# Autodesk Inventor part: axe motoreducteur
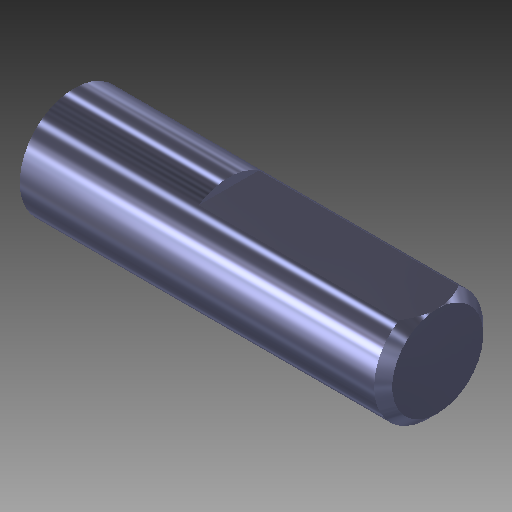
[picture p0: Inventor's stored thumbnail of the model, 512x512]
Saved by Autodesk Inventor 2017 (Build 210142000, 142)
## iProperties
Part Number: axe motoreducteur
Material: Générique
Document SubType Name: Modeling
Designer: ficho
Density: 1 g/cm^3
Appearance: Chrome - Bleu poli
Mass: 0.550661 g
Surface Area: 4.2614 cm^2
Volume: 0.550661 cm^3
Author: ficho
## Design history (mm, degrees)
sketch "Esquisse1"
  geometry: L1 (0, 0)-(0, 2.5); L2 (-0.5, 3)-(-20, 3); L3 (-20, 3)-(-20, 0); L4 (-20, 0)-(0, 0); L5 (0, 2.5)-(-0.5, 3); 1 further point
  constraints: 10 end point, 3 perpendicular, 2 point on line, 1 vertical
  dimensions: "d0" = 3 distance between parallel lines of L2 L4; "d1" = 20 distance between parallel lines of L1 L3; "d2" = 0.5 distance of L1.end point (0, 3); "d3" = 0.5 distance of L2.start point (0, 3) (= d2)
revolve "Révolution1" sketch "Esquisse1" stored, may be unused: angle "d4" = 90 deg
sketch "Esquisse2"
  geometry: L1 (-4.726, 6.51)-(5.094, 6.51); L2 (5.094, 6.51)-(5.094, 2.5); L3 (5.094, 2.5)-(-4.726, 2.5); L4 (-4.726, 2.5)-(-4.726, 6.51); 1 further point
  constraints: 8 end point, 2 parallel, 1 horizontal, 1 perpendicular
  dimensions: "d5" = 2.5 distance from line of L3 point (0, 0)
extrude "Extrusion1" cut sketch "Esquisse2" distance "d6" = 11.5; taper "d7" = 0 deg
node "Solide1"
